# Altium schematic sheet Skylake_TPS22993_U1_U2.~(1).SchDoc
size 431 x 279 mm; Date: Not shown in title block; ApprovedBy: Not shown in title block; CheckedBy: Not shown in title block; Author: Not shown in title block; CompanyName: Not shown in title block; Engineer: Not shown in title block; Organization: Not shown in title block; Address1: Not shown in title block; Address2: Not shown in title block; Address3: Not shown in title block; Address4: Not shown in title block; DocumentNumber: 1; Revision: Use project parameter SCH_Rev; SheetNumber: 1; SheetTotal: 9; PageSetup: Record=PageOptions|CenterHorizontal=True|CenterVertical=True|PrintScale=1.00|XCorrection=1.00|YCorrection=1.00|PrintKind=0|BorderSize=5000000|LeftOffset=0|BottomOffset=0|Orientation=2|PaperLength=1000|PaperWidth=1000|Scale=100|PaperSource=15|PrintQuality=600|MediaType=1|DitherType=10|PaperKind=Letter|PrintScaleMode=1
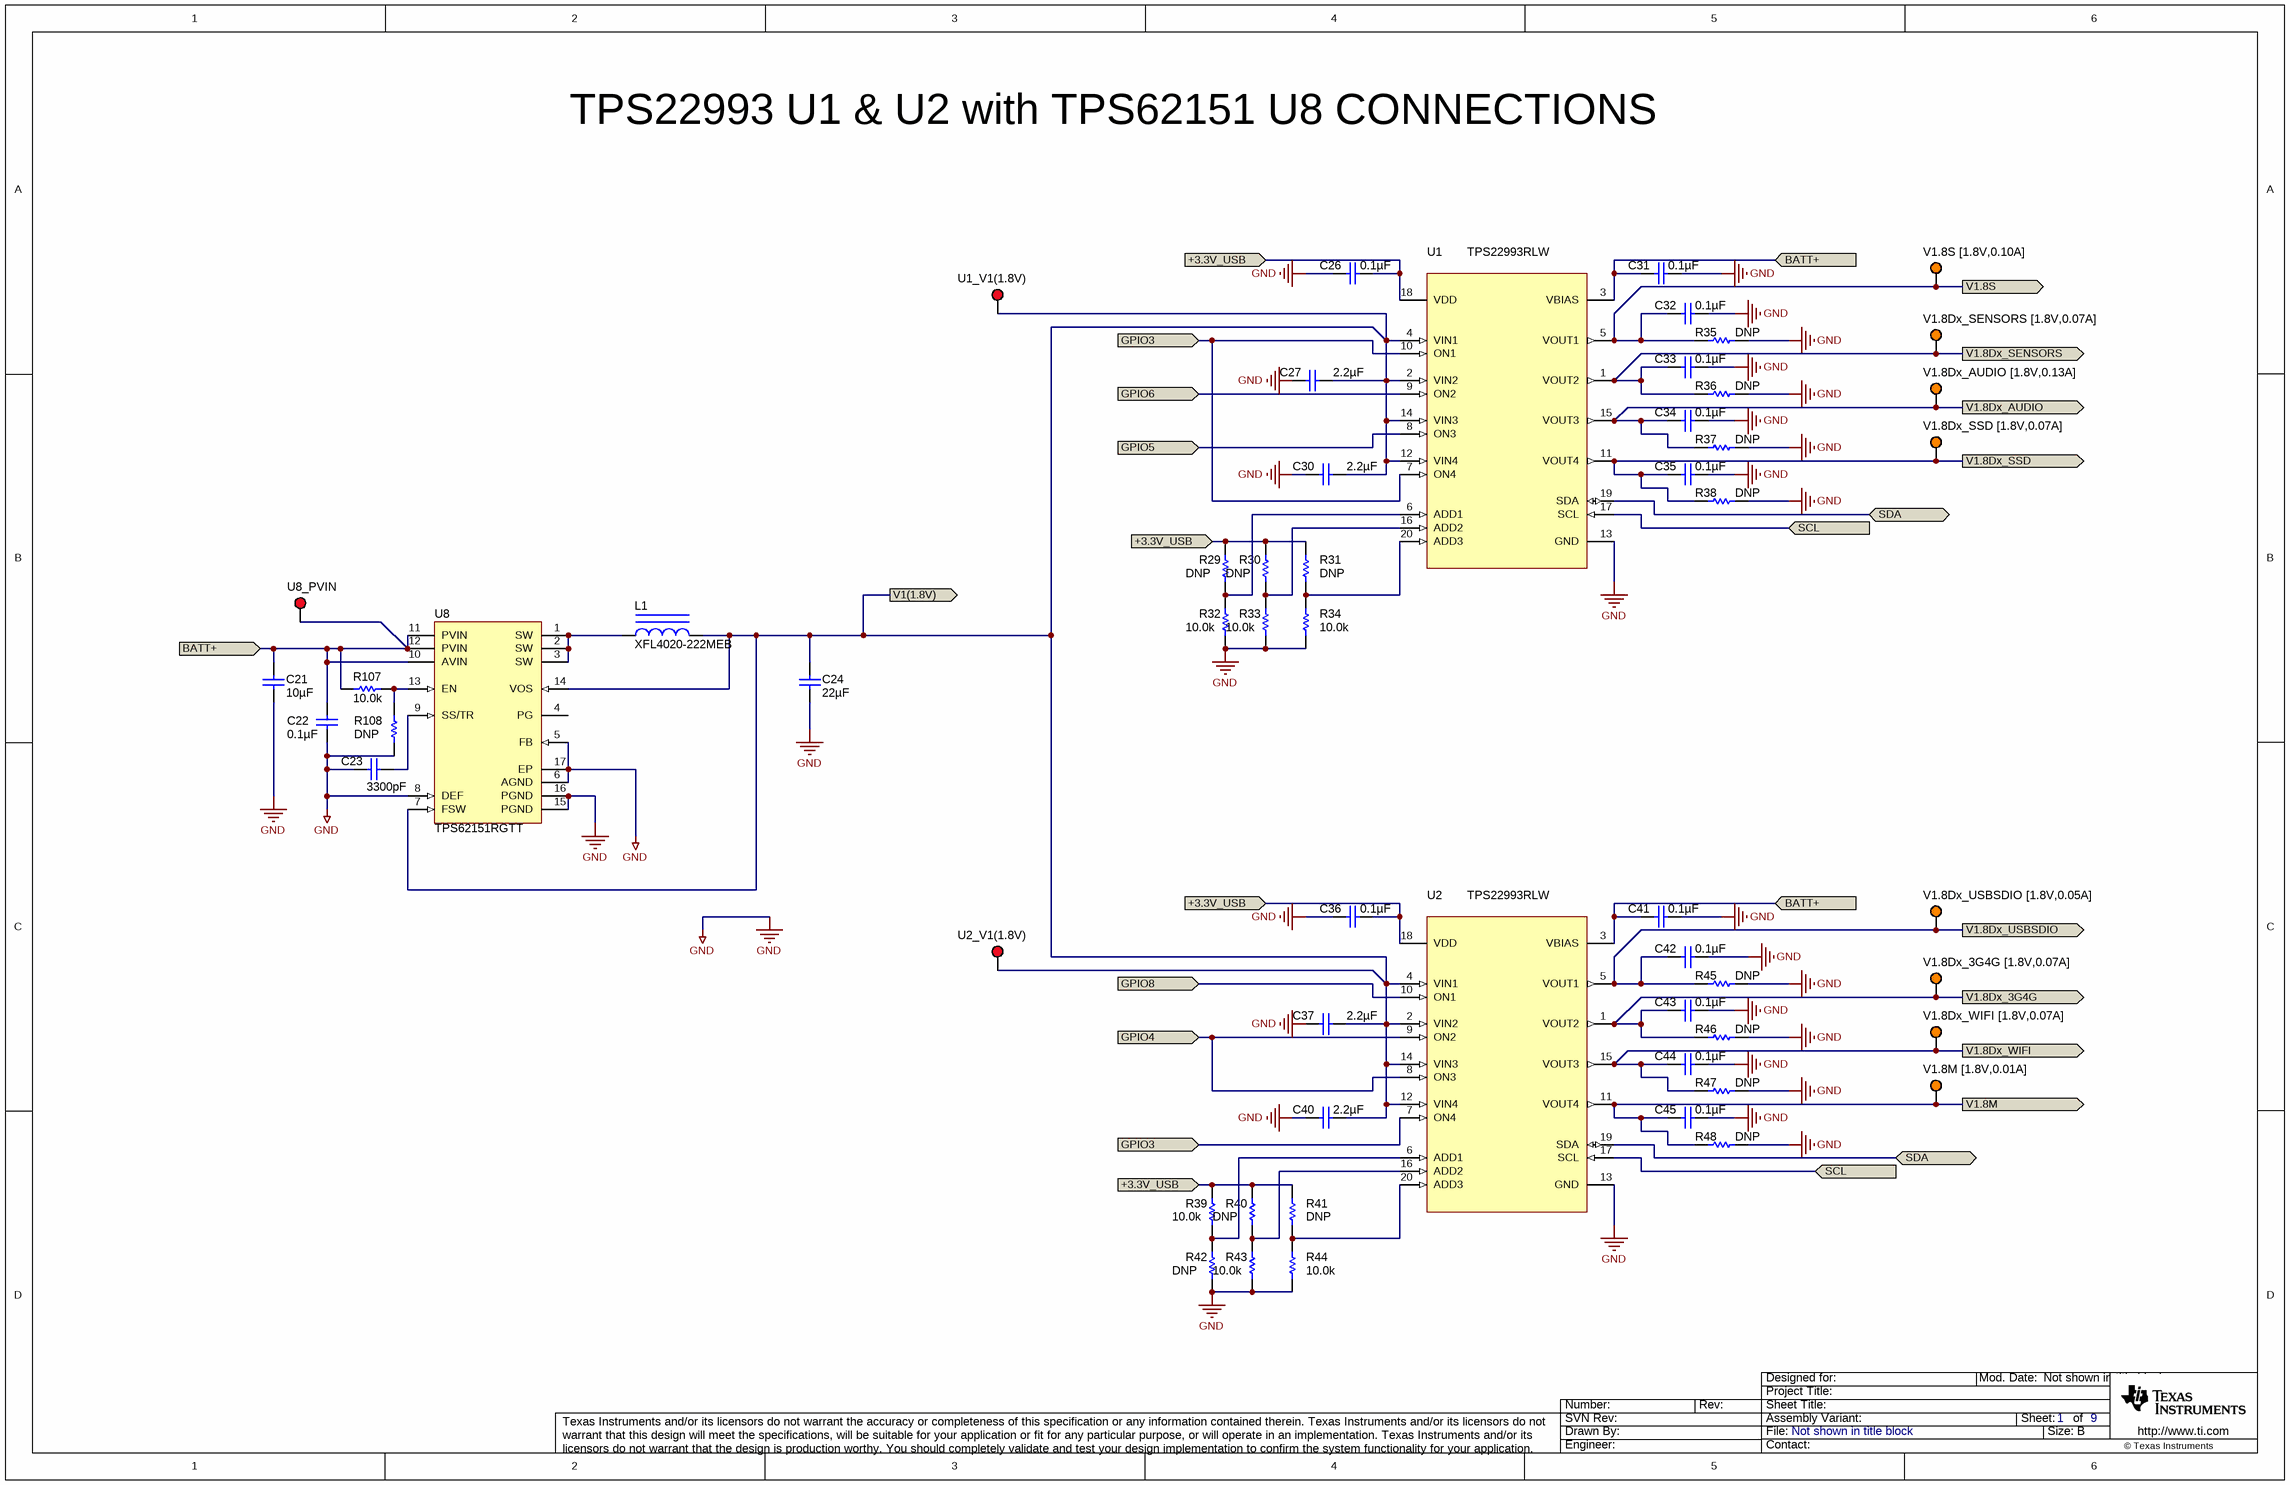
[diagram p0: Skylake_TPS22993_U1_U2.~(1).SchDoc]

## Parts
C21  ValueDisplayed: 10µF  [0805_HV]  (hidden comment: C2012JB1V106K085AC)
C22  ValueDisplayed: 0.1µF  [0805_HV]  (hidden comment: Taiyo Yuden)
C23  ValueDisplayed: 3300pF  [0603]  (hidden comment: C0603C332J3RACTU)
C24  ValueDisplayed: 22µF  [0805_HV]  (hidden comment: C2012X5R1V226M125AC)
C26  ValueDisplayed: 0.1µF  [0603]  (hidden comment: C0603C104K8RACTU)
C27  ValueDisplayed: 2.2µF  [0603]  (hidden comment: GRM188C81A225KE34D)
C30  ValueDisplayed: 2.2µF  [0603]  (hidden comment: GRM188C81A225KE34D)
C31  ValueDisplayed: 0.1µF  [0805_HV]  (hidden comment: GMK212BJ104KGHT)
C32  ValueDisplayed: 0.1µF  [0603]  (hidden comment: C0603C104K8RACTU)
C33  ValueDisplayed: 0.1µF  [0603]  (hidden comment: C0603C104K8RACTU)
C34  ValueDisplayed: 0.1µF  [0603]  (hidden comment: C0603C104K8RACTU)
C35  ValueDisplayed: 0.1µF  [0603]  (hidden comment: C0603C104K8RACTU)
C36  ValueDisplayed: 0.1µF  [0603]  (hidden comment: C0603C104K8RACTU)
C37  ValueDisplayed: 2.2µF  [0603]  (hidden comment: GRM188C81A225KE34D)
C40  ValueDisplayed: 2.2µF  [0603]  (hidden comment: GRM188C81A225KE34D)
C41  ValueDisplayed: 0.1µF  [0805_HV]  (hidden comment: GMK212BJ104KGHT)
C42  ValueDisplayed: 0.1µF  [0603]  (hidden comment: C0603C104K8RACTU)
C43  ValueDisplayed: 0.1µF  [0603]  (hidden comment: C0603C104K8RACTU)
C44  ValueDisplayed: 0.1µF  [0603]  (hidden comment: C0603C104K8RACTU)
C45  ValueDisplayed: 0.1µF  [0603]  (hidden comment: C0603C104K8RACTU)
L1  XFL4020-222MEB  [XFL4020]
R29  value DNP  [0402]  (hidden comment: CRCW040210K0FKED)
R30  value DNP  [0402]  (hidden comment: CRCW040210K0FKED)
R31  value DNP  [0402]  (hidden comment: CRCW040210K0FKED)
R32  value 10.0k  [0402]  (hidden comment: CRCW040210K0FKED)
R33  value 10.0k  [0402]  (hidden comment: CRCW040210K0FKED)
R34  value 10.0k  [0402]  (hidden comment: CRCW040210K0FKED)
R35  value DNP  [1206]  (hidden comment: CRCW120618R0JNEA)
R36  value DNP  [1210M]  (hidden comment: ERJ-14NF25R5U)
R37  value DNP  [1210M]  (hidden comment: ERJ-14NF13R7U)
R38  value DNP  [1210M]  (hidden comment: ERJ-14NF25R5U)
R39  value 10.0k  [0402]  (hidden comment: CRCW040210K0FKED)
R40  value DNP  [0402]  (hidden comment: CRCW040210K0FKED)
R41  value DNP  [0402]  (hidden comment: CRCW040210K0FKED)
R42  value DNP  [0402]  (hidden comment: CRCW040210K0FKED)
R43  value 10.0k  [0402]  (hidden comment: CRCW040210K0FKED)
R44  value 10.0k  [0402]  (hidden comment: CRCW040210K0FKED)
R45  value DNP  [1206]  (hidden comment: CRCW120636R0JNEA)
R46  value DNP  [1210M]  (hidden comment: ERJ-14NF25R5U)
R47  value DNP  [1210M]  (hidden comment: ERJ-14NF25R5U)
R48  value DNP  [1206]  (hidden comment: CRCW1206180RJNEA)
R107  value 10.0k  [0402]  (hidden comment: CRCW040210K0FKED)
R108  value DNP  [0402]  (hidden comment: CRCW040210K0FKED)
U1  TPS22993RLW  [RLW0020A]
U1_V1(1.8V)  5005  [Keystone5005]  (value not drawn)
U2  TPS22993RLW  [RLW0020A]
U2_V1(1.8V)  5005  [Keystone5005]  (value not drawn)
U8  TPS62151RGTT  [RGT0016C]
U8_PVIN  5005  [Keystone5005]  (value not drawn)
V1.8Dx_3G4G_[1.8V,0.07A]  5008  [Keystone5008]  (value not drawn)
V1.8Dx_AUDIO_[1.8V,0.13A]  5008  [Keystone5008]  (value not drawn)
V1.8Dx_SENSORS_[1.8V,0.07A]  5008  [Keystone5008]  (value not drawn)
V1.8Dx_SSD_[1.8V,0.07A]  5008  [Keystone5008]  (value not drawn)
V1.8Dx_USBSDIO_[1.8V,0.05A]  5008  [Keystone5008]  (value not drawn)
V1.8Dx_WIFI_[1.8V,0.07A]  5008  [Keystone5008]  (value not drawn)
V1.8M_[1.8V,0.01A]  5008  [Keystone5008]  (value not drawn)
V1.8S_[1.8V,0.10A]  5008  [Keystone5008]  (value not drawn)

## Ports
+3.3V_USB (in), BATT+ (in), GPIO3 (in), GPIO4 (in), GPIO5 (in), GPIO6 (in), GPIO8 (in), SCL (in), SDA (bidir), V1(1.8V) (out), V1.8Dx_3G4G (out), V1.8Dx_AUDIO (out), V1.8Dx_SENSORS (out), V1.8Dx_SSD (out), V1.8Dx_USBSDIO (out), V1.8Dx_WIFI (out), V1.8M (out), V1.8S (out)

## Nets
GND: C21.2 C22.2 C23.2 C24.2 C26.2 C27.2 C30.2 C31.1 C32.1 C33.1 C34.1 C35.1 C36.2 C37.2 C40.2 C41.1 C42.1 C43.1 C44.1 C45.1 R32.1 R33.1 R34.1 R35.2 R36.2 R37.2 R38.2 R42.1 R43.1 R44.1 R45.2 R46.2 R47.2 R48.2 R108.1 U1.13(GND) U2.13(GND) U8.5(FB) U8.6(AGND) U8.8(DEF) U8.15(PGND) U8.16(PGND) U8.17(EP)
+3.3V_USB: C26.1 C36.1 R29.2 R30.2 R31.2 R39.2 R40.2 R41.2 U1.18(VDD) U2.18(VDD) ; port +3.3V_USB
BATT+: C21.1 C22.1 C31.2 C41.2 R107.1 U1.3(VBIAS) U2.3(VBIAS) U8.10(AVIN) U8.11(PVIN) U8.12(PVIN) U8_PVIN.1 ; port BATT+
GPIO3: U1.7(ON4) U1.10(ON1) U2.7(ON4) ; port GPIO3
GPIO4: U2.8(ON3) U2.9(ON2) ; port GPIO4
GPIO5: U1.8(ON3) ; port GPIO5
GPIO6: U1.9(ON2) ; port GPIO6
GPIO8: U2.10(ON1) ; port GPIO8
SCL: U1.17(SCL) U2.17(SCL) ; port SCL
SDA: U1.19(SDA) U2.19(SDA) ; port SDA
V1(1.8V): C24.1 C27.1 C30.1 C37.1 C40.1 L1.2 U1.2(VIN2) U1.4(VIN1) U1.12(VIN4) U1.14(VIN3) U1_V1(1.8V).1 U2.2(VIN2) U2.4(VIN1) U2.12(VIN4) U2.14(VIN3) U2_V1(1.8V).1 U8.7(FSW) U8.14(VOS) ; port V1(1.8V)
V1.8Dx_3G4G: C43.2 R46.1 U2.1(VOUT2) V1.8Dx_3G4G_[1.8V,0.07A].1 ; port V1.8Dx_3G4G
V1.8Dx_AUDIO: C34.2 R37.1 U1.15(VOUT3) V1.8Dx_AUDIO_[1.8V,0.13A].1 ; port V1.8Dx_AUDIO
V1.8Dx_SENSORS: C33.2 R36.1 U1.1(VOUT2) V1.8Dx_SENSORS_[1.8V,0.07A].1 ; port V1.8Dx_SENSORS
V1.8Dx_SSD: C35.2 R38.1 U1.11(VOUT4) V1.8Dx_SSD_[1.8V,0.07A].1 ; port V1.8Dx_SSD
V1.8Dx_USBSDIO: C42.2 R45.1 U2.5(VOUT1) V1.8Dx_USBSDIO_[1.8V,0.05A].1 ; port V1.8Dx_USBSDIO
V1.8Dx_WIFI: C44.2 R47.1 U2.15(VOUT3) V1.8Dx_WIFI_[1.8V,0.07A].1 ; port V1.8Dx_WIFI
V1.8M: C45.2 R48.1 U2.11(VOUT4) V1.8M_[1.8V,0.01A].1 ; port V1.8M
V1.8S: C32.2 R35.1 U1.5(VOUT1) V1.8S_[1.8V,0.10A].1 ; port V1.8S
NetC23_1: C23.1 U8.9(SS/TR)
NetL1_1: L1.1 U8.1(SW) U8.2(SW) U8.3(SW)
NetR29_1: R29.1 R32.2 U1.6(ADD1)
NetR30_1: R30.1 R33.2 U1.16(ADD2)
NetR31_1: R31.1 R34.2 U1.20(ADD3)
NetR39_1: R39.1 R42.2 U2.6(ADD1)
NetR40_1: R40.1 R43.2 U2.16(ADD2)
NetR41_1: R41.1 R44.2 U2.20(ADD3)
NetR107_2: R107.2 R108.2 U8.13(EN)

Not connected (* = marked no-connect by the designer): U8 4(PG)

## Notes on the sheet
- TPS22993 U1 & U2 with TPS62151 U8 CONNECTIONS

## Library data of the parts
C21 = C2012X5R1E106K125AB: CAP, CERM, 10uF, 35V, +/-10%, X5R, 0805; Manufacturer: TDK; Polarized: N; CompType: Capacitor; U/M: EA; Cap_F: 0.00001; Tolerance_%: 10; Value1: Unknown; VDC_V: 35; TaMin_C: -55; TaMax_C: 85; Cap_Case: 0805
C22 = GRM21BR61E226ME44: CAP, CERM, 0.1uF, 35V, +/-20%, X5R, 0603; Manufacturer: TDK Corporation; Polarized: N; CompType: Capacitor; U/M: EA; Tolerance_%: 20; Value1: Unknown; VDC_V: 35; TaMin_C: -55; TaMax_C: 85; Cap_Case: 0603
C23 = C0603C332K5RACTU: CAP, CERM, 3300pF, 25V, +/-5%, X7R, 0603; Manufacturer: Kemet; Polarized: N; CompType: Capacitor; U/M: EA; Cap_F: 0.0000000033; Tolerance_%: 5; Value1: Unknown; VDC_V: 25; TaMin_C: -55; TaMax_C: 125
C24 = GRM21BR61E226ME44: CAP, CERM, 22uF, 35V, +/-20%, X5R, 0805; Manufacturer: TDK Corporation; Polarized: N; CompType: Capacitor; U/M: EA; Cap_F: 0.000022; Tolerance_%: 20; Value1: Unknown; VDC_V: 35; TaMin_C: -55; TaMax_C: 85; Cap_Case: 0805
C26 C32-C36 C42-C45 = GRM188R71C104KA01D: CAP, CERM, 0.1uF, 10V, +/-10%, X7R, 0603; Manufacturer: Kemet; Polarized: N; CompType: Capacitor; U/M: EA; Cap_F: 0.0000001; Tolerance_%: 10; Value1: Unknown; TaMin_C: -55; TaMax_C: 125
C27 C30 C37 C40 = GRM188C81A225KE34D: CAP, CERM, 2.2uF, 10V, +/-10%, X6S, 0603; Manufacturer: MuRata; Polarized: N; CompType: Capacitor; U/M: EA; Cap_F: 0.0000022; Tolerance_%: 10; Value1: Unknown; TaMin_C: -55; TaMax_C: 105
C31 C41 = GRM21BR61E226ME44: CAP, CERM, 0.1uF, 35V, +/-20%, X5R, 0805; Manufacturer: Taiyo Yuden; Polarized: N; CompType: Capacitor; U/M: EA; Cap_F: 0.000022; Tolerance_%: 20; Value1: Unknown; VDC_V: 35; TaMin_C: -55; TaMax_C: 85; Cap_Case: 0805
L1 = XFL4020-222MEB: Inductor, Shielded, Composite, 2.2uH, 3.7A, 0.02 ohm, SMD; Manufacturer: Coilcraft; Ind_H: 2.2E-6; ValueDisplayed: 2.2µH; Imax_A: 3.7; Irms: 8A @ 40C rise; Isat: 3.7A @ 30% inductance drop; DCR_ohm: 0.02; U/M: EA
R29-R31 R40-R42 R108 = CRCW040210K0FKED: RES, DNP, 1%, 0.063W, 0402; Manufacturer: Vishay-Dale; CompType: Resistor; Res_ohm: 10000; Value_Code: 10k0; Tolerance_%: 1; Power_W: 0.063; VDC_V: 50; TempCo: 100 ppm/C; EIA_Code: E96; U/M: EA
R32-R34 R39 R43 R44 R107 = CRCW040210K0FKED: RES, 10.0k ohm, 1%, 0.063W, 0402; Manufacturer: Vishay-Dale; CompType: Resistor; Res_ohm: 10000; Value_Code: 10k0; Tolerance_%: 1; Power_W: 0.063; VDC_V: 50; TempCo: 100 ppm/C; EIA_Code: E96; U/M: EA
R35 = CRCW120618R0JNEA: RES, DNP, 5%, 0.25W, 1206; Manufacturer: Vishay-Dale; CompType: Resistor; Res_ohm: 18; Value_Code: 18R0; Tolerance_%: 5; Power_W: 0.25; VDC_V: 200; TempCo: 200 ppm/C; EIA_Code: E24; U/M: EA
R36-R38 R46 R47 = ERJ14NF1001U: RES, DNP, 1%, 0.5W, 1210; Manufacturer: Panasonic; CompType: Resistor; Res_ohm: 1000; Tolerance_%: 1; Power_W: 0.5; VDC_V: 22; TempCo: 100 ppm/C; EIA_Code: E96; U/M: EA
R45 = CRCW120618R0JNEA: RES, DNP, 5%, 0.25W, 1206; Manufacturer: Vishay-Dale; CompType: Resistor; Res_ohm: 36; Value_Code: 36R0; Tolerance_%: 5; Power_W: 0.25; VDC_V: 200; TempCo: 200 ppm/C; EIA_Code: E24; U/M: EA
R48 = CRCW1206180RJNEA: RES, DNP, 5%, 0.25W, 1206; Manufacturer: Vishay-Dale; CompType: Resistor; Res_ohm: 180; Value_Code: 180R; Tolerance_%: 5; Power_W: 0.25; VDC_V: 200; TempCo: 200 ppm/C; EIA_Code: E24; U/M: EA
U1 U2 = TPS22993RLW: Quad Channel Load Switch with GPIO and I2C Control, RLW0020A; Alternate Manufacturer: None; Manufacturer: Texas Instruments; SymbolCreator: a0411947; CompType: IC; U/M: EA
U1_V1(1.8V) U2_V1(1.8V) U8_PVIN = 5005: Test Point, Compact, Red, TH; Manufacturer: Keystone; CompType: Test Point Loop; U/M: EA
U8 = TPS62151RGTT: Buck Step Down Regulator with 3 to 17 V Input and 1.8 V Output, -40 to 85 degC, 16-Pin QFN (RGT), Green (RoHS & no Sb/Br); Manufacturer: Texas Instruments; Alternate Manufacturer: None; Alternate PartNumber: Equivalent; Duty Cycle(Max)(%): 90; Iout(Max)(A): 1; Iq(Typ)(mA): 0.017; Preset Vout(V): 1.8; Rating: Catalog; SubFamily: Step-Down Regulator; Switch Current Limit(Typ)(A): 1.7; Synchronous Rectification: TRUE; Vin(Max)(V): 17; Vin(Min)(V): 3
V1.8Dx_3G4G_[1.8V,0.07A] V1.8Dx_AUDIO_[1.8V,0.13A] V1.8Dx_SENSORS_[1.8V,0.07A] V1.8Dx_SSD_[1.8V,0.07A] V1.8Dx_USBSDIO_[1.8V,0.05A] V1.8Dx_WIFI_[1.8V,0.07A] V1.8M_[1.8V,0.01A] V1.8S_[1.8V,0.10A] = 5008: Test Point, Compact, Orange, TH; Manufacturer: Keystone; CompType: Test Point Loop; U/M: EA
